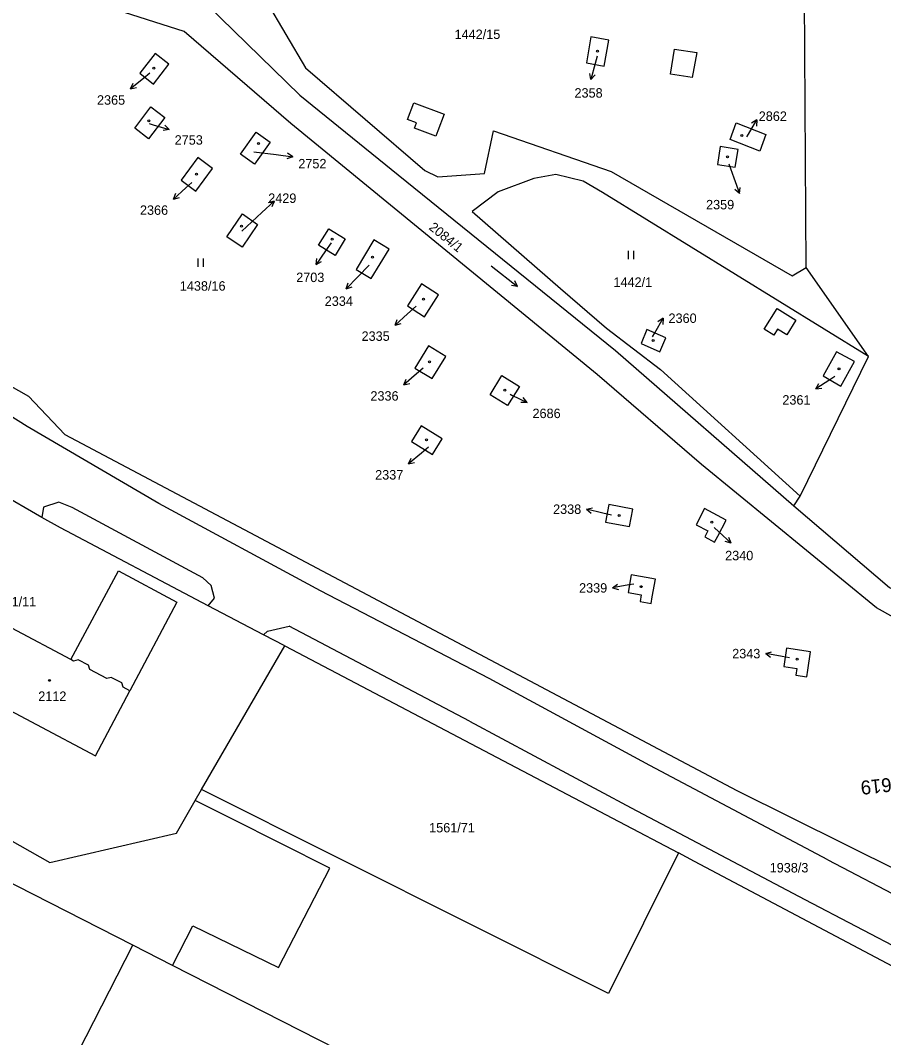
# Model space of a CAD drawing. Extents: x -793666 to -785424, y -1118958 to -1108761.
# Drawn here: x -792788.6 to -792633.4, y -1110488.5 to -1110305.6 of the extents above; entities that cross this region are included whole.
import ezdxf

# ---------------------------------------------------------------- set-up
doc = ezdxf.new("R2010")
doc.units = 0
for name, color, linetype in [('1', 7, 'Continuous'), ('Hranice parcel', 7, 'Continuous'), ('Parcelní čísla', 7, 'Continuous'), ('Pop  PČ popisy', 7, 'Continuous'), ('Vnitřní kresba', 7, 'Continuous'), ('Značky budov', 7, 'Continuous'), ('Značky kultur', 7, 'Continuous')]:
    doc.layers.add(name, color=color, linetype=linetype)

msp = doc.modelspace()

# ---------------------------------------------------------------- linework, layer by layer
at = {"layer": 'Hranice parcel'}
for p, q in [((-792647.35, -1110350.05), (-792647.69, -1110293.54)), ((-792636.1, -1110366.06), (-792647.35, -1110350.05)), ((-792648.42, -1110391.17), (-792636.1, -1110366.06)), ((-792649.52, -1110392.89), (-792648.42, -1110391.17)), ((-792756.01, -1110443.91), (-792741.07, -1110418.09)), ((-792741.07, -1110418.09), (-792681.03, -1110449.67)), ((-792757.16, -1110445.89), (-792756.01, -1110443.91)), ((-792682.88, -1110480.58), (-792756.01, -1110443.91)), ((-792681.03, -1110449.67), (-792670.27, -1110455.33)), ((-792670.27, -1110455.33), (-792682.88, -1110480.58))]:
    msp.add_line(p, q, dxfattribs=at)
for points in [[(-792810.95, -1110280.9), (-792780.07, -1110294.56), (-792755.03, -1110302.83), (-792738.35, -1110319.04), (-792720.66, -1110333.41), (-792681.61, -1110364.96), (-792649.52, -1110392.89)], [(-792614.4, -1110416.41), (-792624.78, -1110416.77), (-792634.65, -1110411.27), (-792666.12, -1110385.5), (-792684.9, -1110369.28), (-792739.95, -1110324.15), (-792759.16, -1110307.61), (-792800.59, -1110294.35), (-792820.87, -1110289.8)], [(-792747.96, -1110296.1), (-792737.31, -1110314.17), (-792715.9, -1110332.58), (-792713.52, -1110333.73), (-792705.15, -1110333.15), (-792703.51, -1110325.45), (-792682.4, -1110332.77), (-792649.82, -1110351.57), (-792647.35, -1110350.05)], [(-792683.65, -1110313.87), (-792682.78, -1110309.16), (-792686.01, -1110308.57), (-792686.83, -1110313.24), (-792683.65, -1110313.87)], [(-792761.88, -1110313.51), (-792764.34, -1110311.58), (-792767.13, -1110315.13), (-792764.67, -1110317.07), (-792761.88, -1110313.51)], [(-792765.13, -1110321.18), (-792762.61, -1110323.08), (-792765.53, -1110326.91), (-792768.03, -1110325.01), (-792765.13, -1110321.18)], [(-792654.56, -1110326.13), (-792655.68, -1110329.11), (-792661, -1110327.03), (-792659.9, -1110324.05), (-792654.56, -1110326.13)], [(-792746.19, -1110325.73), (-792743.69, -1110327.49), (-792746.48, -1110331.45), (-792748.99, -1110329.68), (-792746.19, -1110325.73)], [(-792660.09, -1110332.03), (-792659.56, -1110328.83), (-792662.76, -1110328.31), (-792663.29, -1110331.51), (-792660.09, -1110332.03)], [(-792754.04, -1110332.27), (-792756.69, -1110330.29), (-792759.71, -1110334.33), (-792757.06, -1110336.31), (-792754.04, -1110332.27)], [(-792636.1, -1110366.06), (-792683.96, -1110336.56), (-792687.43, -1110334.55), (-792692.33, -1110333.31), (-792696.26, -1110334.03), (-792702.69, -1110336.46), (-792707.37, -1110339.98), (-792691.47, -1110353.8), (-792683.2, -1110360.99), (-792673.5, -1110368.41), (-792648.42, -1110391.17)], [(-792861.96, -1110336.71), (-792834.85, -1110346.23), (-792831.02, -1110348.4), (-792787.15, -1110373.19), (-792780.58, -1110380.1), (-792659.8, -1110444.12), (-792610.94, -1110468.39)], [(-792751.45, -1110344.53), (-792748.68, -1110340.41), (-792745.94, -1110342.3), (-792748.74, -1110346.39), (-792751.45, -1110344.53)], [(-792734.97, -1110346.04), (-792733.15, -1110343.08), (-792730.17, -1110344.92), (-792732.02, -1110347.9), (-792734.97, -1110346.04)], [(-792725.02, -1110345.09), (-792728.23, -1110350.44), (-792725.55, -1110352.05), (-792722.29, -1110346.73), (-792725.02, -1110345.09)], [(-792719.01, -1110356.92), (-792715.96, -1110358.91), (-792713.41, -1110354.99), (-792716.45, -1110353), (-792719.01, -1110356.92)], [(-792676.99, -1110363.73), (-792673.63, -1110365.2), (-792672.54, -1110362.71), (-792675.94, -1110361.21), (-792676.99, -1110363.73)], [(-792715.22, -1110364.12), (-792717.68, -1110368.16), (-792714.55, -1110370.01), (-792712.08, -1110366.03), (-792715.22, -1110364.12)], [(-792638.64, -1110366.98), (-792641.86, -1110365.21), (-792644.29, -1110369.56), (-792641.07, -1110371.36), (-792638.64, -1110366.98)], [(-792698.86, -1110371.43), (-792701.03, -1110374.88), (-792704.14, -1110372.96), (-792702.03, -1110369.5), (-792698.86, -1110371.43)], [(-792714.51, -1110383.69), (-792712.75, -1110380.89), (-792716.51, -1110378.54), (-792718.29, -1110381.36), (-792714.51, -1110383.69)], [(-792784.72, -1110394.98), (-792792.65, -1110390.44), (-792794.58, -1110389.34)], [(-792679.09, -1110396.64), (-792678.49, -1110393.51), (-792682.79, -1110392.67), (-792683.39, -1110395.82), (-792679.09, -1110396.64)], [(-792665.56, -1110398.49), (-792663.79, -1110399.43), (-792663.23, -1110398.37), (-792661.7, -1110395.49), (-792665.58, -1110393.41), (-792667.12, -1110396.3), (-792665, -1110397.43), (-792665.56, -1110398.49)], [(-792649.52, -1110392.89), (-792632.37, -1110407.62), (-792623.11, -1110412.52), (-792614.81, -1110411.53)], [(-792754.82, -1110410.86), (-792781.4, -1110396.88), (-792784.72, -1110394.98)], [(-792676.97, -1110408.94), (-792677.19, -1110410.12), (-792675.21, -1110410.48), (-792674.99, -1110409.3), (-792674.41, -1110406.08), (-792678.76, -1110405.29), (-792679.35, -1110408.5), (-792676.97, -1110408.94)], [(-792741.07, -1110418.09), (-792744.86, -1110416.1), (-792754.82, -1110410.86)], [(-792778.22, -1110420.57), (-792779.01, -1110420.81), (-792779.54, -1110420.53), (-792790.14, -1110414.9), (-792796.33, -1110426.57), (-792775.11, -1110437.84), (-792768.93, -1110426.16), (-792770.13, -1110425.53), (-792770.37, -1110424.73), (-792772.25, -1110423.75), (-792773.04, -1110423.98), (-792776.1, -1110422.36), (-792776.35, -1110421.57), (-792778.22, -1110420.57)], [(-792646.52, -1110419.16), (-792650.87, -1110418.51), (-792651.35, -1110421.79), (-792648.99, -1110422.14), (-792649.17, -1110423.34), (-792647.18, -1110423.63), (-792647, -1110422.44), (-792646.52, -1110419.16)], [(-792827.45, -1110421.43), (-792799.1, -1110448.12), (-792783.32, -1110457.02), (-792760.54, -1110451.74), (-792757.16, -1110445.89)], [(-792761.23, -1110475.55), (-792768.36, -1110471.92), (-792821.87, -1110444.63), (-792833.35, -1110467.07), (-792836.92, -1110465.24), (-792839.29, -1110466.05), (-792845.03, -1110477.35), (-792844.59, -1110477.44), (-792848.33, -1110485.09), (-792848.86, -1110484.89), (-792854.67, -1110496.33), (-792853.9, -1110498.34), (-792850.3, -1110500.18), (-792861.74, -1110522.54), (-792808.28, -1110549.91), (-792801.15, -1110553.55)], [(-792761.23, -1110475.55), (-792757.59, -1110468.44), (-792742.2, -1110475.94), (-792732.96, -1110458.09), (-792750.58, -1110449.21), (-792757.16, -1110445.89)], [(-792617.47, -1110483.28), (-792667.41, -1110456.84), (-792670.27, -1110455.33)], [(-792721.79, -1110511.93), (-792715.21, -1110499), (-792761.23, -1110475.55)]]:
    msp.add_lwpolyline(points, dxfattribs=at)
at = {"layer": 'Pop  PČ popisy'}
for p, q in [((-792684.88, -1110312.03), (-792685.24, -1110313.35)), ((-792685.24, -1110313.35), (-792686.02, -1110316.25)), ((-792765.3, -1110315.11), (-792766.47, -1110316.06)), ((-792686.02, -1110316.25), (-792686.24, -1110315.15)), ((-792686.02, -1110316.25), (-792685.27, -1110315.41)), ((-792766.47, -1110316.06), (-792768.8, -1110317.95)), ((-792768.8, -1110317.95), (-792768.34, -1110316.93)), ((-792768.8, -1110317.95), (-792767.71, -1110317.71)), ((-792765.46, -1110324.17), (-792764.69, -1110324.4)), ((-792764.69, -1110324.4), (-792761.81, -1110325.23)), ((-792761.81, -1110325.23), (-792762.63, -1110324.47)), ((-792657.71, -1110326.1), (-792656.21, -1110323.5)), ((-792656.21, -1110323.5), (-792657.14, -1110324.12)), ((-792656.21, -1110323.5), (-792656.28, -1110324.62)), ((-792761.81, -1110325.23), (-792762.91, -1110325.43)), ((-792657.97, -1110326.56), (-792657.71, -1110326.1)), ((-792746.59, -1110329.28), (-792742.59, -1110329.76)), ((-792742.59, -1110329.76), (-792739.61, -1110330.13)), ((-792739.61, -1110330.13), (-792740.67, -1110330.5)), ((-792739.61, -1110330.13), (-792740.54, -1110329.51)), ((-792661.24, -1110331.41), (-792660.33, -1110333.95)), ((-792660.33, -1110333.95), (-792659.3, -1110336.77)), ((-792758.85, -1110335.74), (-792761.08, -1110337.75)), ((-792757.77, -1110334.77), (-792758.85, -1110335.74)), ((-792659.3, -1110336.77), (-792659.18, -1110335.66)), ((-792761.08, -1110337.75), (-792760.67, -1110336.71)), ((-792761.08, -1110337.75), (-792760, -1110337.45)), ((-792659.3, -1110336.77), (-792660.12, -1110336)), ((-792745.17, -1110340.15), (-792742.97, -1110338.1)), ((-792742.97, -1110338.1), (-792744.05, -1110338.42)), ((-792742.97, -1110338.1), (-792743.37, -1110339.15)), ((-792748.79, -1110343.53), (-792745.17, -1110340.15)), ((-792732.7, -1110345.63), (-792733.71, -1110347.06)), ((-792733.71, -1110347.06), (-792735.43, -1110349.52)), ((-792735.43, -1110349.52), (-792735.27, -1110348.41)), ((-792735.43, -1110349.52), (-792734.45, -1110348.99)), ((-792725.87, -1110349.61), (-792727.91, -1110351.71)), ((-792727.91, -1110351.71), (-792729.99, -1110353.87)), ((-792729.99, -1110353.87), (-792729.66, -1110352.8)), ((-792729.99, -1110353.87), (-792728.94, -1110353.5)), ((-792717.41, -1110356.98), (-792719.01, -1110358.41)), ((-792719.01, -1110358.41), (-792721.24, -1110360.42)), ((-792721.24, -1110360.42), (-792720.83, -1110359.38)), ((-792674.55, -1110361.78), (-792673.05, -1110359.18)), ((-792673.05, -1110359.18), (-792673.98, -1110359.8)), ((-792673.05, -1110359.18), (-792673.12, -1110360.3)), ((-792721.24, -1110360.42), (-792720.16, -1110360.12)), ((-792674.96, -1110362.49), (-792674.55, -1110361.78)), ((-792716.16, -1110368.13), (-792717.39, -1110369.2)), ((-792717.39, -1110369.2), (-792719.66, -1110371.17)), ((-792719.66, -1110371.17), (-792719.23, -1110370.13)), ((-792643.08, -1110370.23), (-792645.6, -1110371.86)), ((-792642.18, -1110369.64), (-792643.08, -1110370.23)), ((-792719.66, -1110371.17), (-792718.57, -1110370.89)), ((-792645.6, -1110371.86), (-792645.03, -1110370.9)), ((-792645.6, -1110371.86), (-792644.48, -1110371.74)), ((-792700.52, -1110372.83), (-792700.21, -1110372.98)), ((-792700.21, -1110372.98), (-792697.51, -1110374.3)), ((-792697.51, -1110374.3), (-792698.63, -1110374.31)), ((-792697.51, -1110374.3), (-792698.19, -1110373.41)), ((-792716.5, -1110383.43), (-792718.8, -1110385.36)), ((-792715.24, -1110382.38), (-792716.5, -1110383.43)), ((-792718.8, -1110385.36), (-792718.35, -1110384.33)), ((-792718.8, -1110385.36), (-792717.71, -1110385.1)), ((-792686.81, -1110393.52), (-792685.73, -1110393.26)), ((-792683.89, -1110394.2), (-792686.81, -1110393.52)), ((-792686.81, -1110393.52), (-792685.95, -1110394.24)), ((-792682.33, -1110394.57), (-792683.89, -1110394.2)), ((-792663.85, -1110396.79), (-792663.02, -1110397.58)), ((-792663.02, -1110397.58), (-792660.83, -1110399.63)), ((-792660.83, -1110399.63), (-792661.9, -1110399.31)), ((-792660.83, -1110399.63), (-792661.22, -1110398.58)), ((-792682.15, -1110407.66), (-792681.25, -1110406.99)), ((-792679.19, -1110407.14), (-792682.15, -1110407.66)), ((-792678.29, -1110406.98), (-792679.19, -1110407.14)), ((-792682.15, -1110407.66), (-792681.07, -1110407.98)), ((-792654.6, -1110419.47), (-792653.53, -1110419.15)), ((-792651.65, -1110419.99), (-792654.6, -1110419.47)), ((-792654.6, -1110419.47), (-792653.71, -1110420.14)), ((-792650.34, -1110420.22), (-792651.65, -1110419.99))]:
    msp.add_line(p, q, dxfattribs=at)
at = {"layer": 'Vnitřní kresba'}
for p, q in [((-792671.7, -1110315.3), (-792670.97, -1110310.77)), ((-792670.97, -1110310.77), (-792666.99, -1110311.41)), ((-792666.99, -1110311.41), (-792667.83, -1110315.89)), ((-792667.83, -1110315.89), (-792671.7, -1110315.3)), ((-792719.02, -1110323.44), (-792717.88, -1110320.43)), ((-792717.88, -1110320.43), (-792712.43, -1110322.51)), ((-792712.43, -1110322.51), (-792713.55, -1110325.5)), ((-792717.38, -1110324.06), (-792719.02, -1110323.44)), ((-792717.72, -1110324.98), (-792717.38, -1110324.06)), ((-792713.9, -1110326.43), (-792717.72, -1110324.98)), ((-792713.55, -1110325.5), (-792713.9, -1110326.43)), ((-792654.87, -1110361.14), (-792652.54, -1110357.42)), ((-792652.54, -1110357.42), (-792649.16, -1110359.55)), ((-792649.16, -1110359.55), (-792650.77, -1110362.16)), ((-792653.11, -1110362.21), (-792654.87, -1110361.14)), ((-792652.45, -1110361.13), (-792653.11, -1110362.21)), ((-792650.77, -1110362.16), (-792652.45, -1110361.13)), ((-792787.39, -1110378.66), (-792807.54, -1110365.86)), ((-792763.7, -1110392.48), (-792787.39, -1110378.66)), ((-792781.67, -1110392.27), (-792784.44, -1110393.16)), ((-792779.28, -1110393.19), (-792781.67, -1110392.27)), ((-792734.65, -1110408.19), (-792763.7, -1110392.48)), ((-792784.44, -1110393.16), (-792784.72, -1110394.98)), ((-792755.78, -1110405.83), (-792779.28, -1110393.19)), ((-792779.54, -1110420.53), (-792770.97, -1110404.57)), ((-792770.97, -1110404.57), (-792760.47, -1110410.2)), ((-792754.27, -1110407.23), (-792755.78, -1110405.83)), ((-792753.69, -1110409.5), (-792754.27, -1110407.23)), ((-792704.32, -1110423.95), (-792734.65, -1110408.19)), ((-792760.47, -1110410.2), (-792768.93, -1110426.16)), ((-792754.82, -1110410.86), (-792753.69, -1110409.5)), ((-792744.17, -1110415.42), (-792740.24, -1110414.55)), ((-792707.83, -1110431.64), (-792740.24, -1110414.55)), ((-792744.17, -1110415.42), (-792744.86, -1110416.1)), ((-792675.45, -1110439.61), (-792704.32, -1110423.95)), ((-792707.83, -1110431.64), (-792678.77, -1110447.22)), ((-792643.45, -1110456.57), (-792675.45, -1110439.61)), ((-792678.77, -1110447.22), (-792647.57, -1110463.72)), ((-792643.45, -1110456.57), (-792609.51, -1110474.26)), ((-792647.57, -1110463.72), (-792608.66, -1110484.08))]:
    msp.add_line(p, q, dxfattribs=at)
msp.add_lwpolyline([(-792784.44, -1110508.55), (-792786.55, -1110507.47), (-792768.36, -1110471.92)], dxfattribs=at)
at = {"layer": 'Značky budov'}
for centre in [(-792684.82, -1110311.16), (-792764.6, -1110314.21), (-792765.5, -1110323.7), (-792658.87, -1110326.32), (-792745.8, -1110327.77), (-792661.46, -1110330.16), (-792756.93, -1110333.25), (-792748.86, -1110342.62), (-792732.52, -1110344.96), (-792725.27, -1110348.21), (-792716.1, -1110355.73), (-792674.81, -1110363.16), (-792715.05, -1110367.01), (-792641.42, -1110368.27), (-792701.48, -1110372.11), (-792715.58, -1110381.06), (-792680.95, -1110394.65), (-792664.27, -1110395.86), (-792677, -1110407.44), (-792648.92, -1110420.5), (-792783.33, -1110424.29)]:
    msp.add_circle(centre, 0.175, dxfattribs=at)
at = {"layer": 'Značky kultur'}
for p, q in [((-792756.65, -1110349.94), (-792756.65, -1110348.44)), ((-792755.65, -1110349.94), (-792755.65, -1110348.44)), ((-792679.29, -1110348.58), (-792679.29, -1110347.08)), ((-792678.29, -1110348.58), (-792678.29, -1110347.08)), ((-792703.96, -1110349.77), (-792699.23, -1110353.46)), ((-792699.23, -1110353.46), (-792700.31, -1110353.26)), ((-792699.23, -1110353.46), (-792699.69, -1110352.47))]:
    msp.add_line(p, q, dxfattribs=at)

# ---------------------------------------------------------------- texts
at = {"layer": '1'}
msp.add_text('km 22,971 619', height=2.5, rotation=186.4259, dxfattribs=at).set_placement((-792615.67, -1110439.93))
at = {"layer": 'Parcelní čísla'}
for s, p in [('1442/15', (-792710.53, -1110308.97)), ('2365', (-792774.81, -1110320.78)), ('2358', (-792688.97, -1110319.51)), ('2862', (-792655.85, -1110323.69)), ('2753', (-792760.85, -1110327.97)), ('2752', (-792738.62, -1110332.23)), ('2429', (-792744.03, -1110338.44)), ('2366', (-792767.09, -1110340.58)), ('2359', (-792665.32, -1110339.6)), ('2703', (-792739, -1110352.67)), ('1442/1', (-792681.97, -1110353.54)), ('1438/16', (-792759.92, -1110354.22)), ('2334', (-792733.87, -1110356.95)), ('2360', (-792672.07, -1110360.02)), ('2335', (-792727.25, -1110363.24)), ('2336', (-792725.66, -1110374)), ('2361', (-792651.6, -1110374.71)), ('2686', (-792696.52, -1110377.13)), ('2337', (-792724.81, -1110388.18)), ('2338', (-792692.82, -1110394.36)), ('2340', (-792661.89, -1110402.7)), ('2339', (-792688.15, -1110408.52)), ('1561/11', (-792793.96, -1110410.99)), ('2343', (-792660.62, -1110420.33)), ('2112', (-792785.37, -1110427.99)), ('1561/71', (-792715.1, -1110451.63)), ('1938/3', (-792653.88, -1110458.83))]:
    msp.add_text(s, height=1.7, dxfattribs=at).set_placement(p)
msp.add_text('2084/1', height=1.7, rotation=321, dxfattribs=at).set_placement((-792715.28, -1110343.07))

doc.saveas('drawing.dxf')
